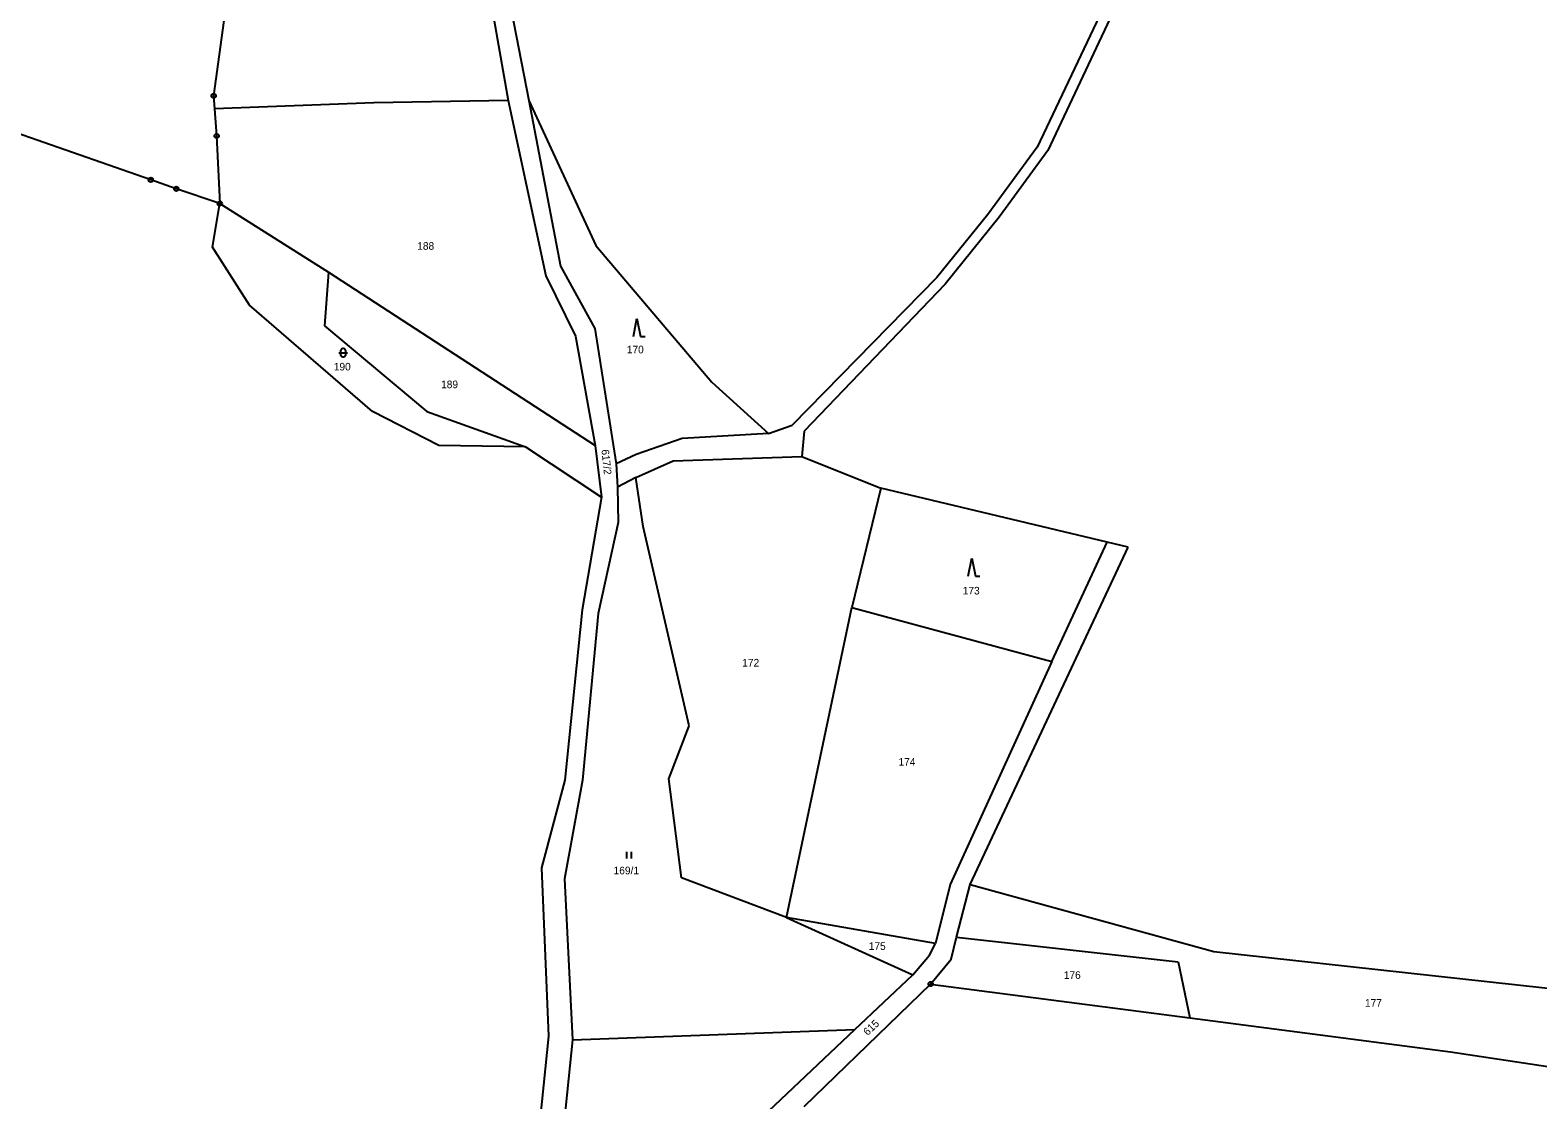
# Model space of a CAD drawing. Extents: x -794421 to -792735, y -1117671 to -1115559.
# Drawn here: x -793585 to -793247.9, y -1116038.2 to -1115798.8 of the extents above; entities that cross this region are included whole.
import ezdxf

# ---------------------------------------------------------------- set-up
doc = ezdxf.new("R2010")
doc.units = 0
for name, color, linetype in [('Vrstva 1', 7, 'Continuous'), ('Vrstva 14', 7, 'Continuous'), ('Vrstva 23', 7, 'Continuous'), ('Vrstva 28', 7, 'Continuous'), ('Vrstva 3', 7, 'Continuous')]:
    doc.layers.add(name, color=color, linetype=linetype)

msp = doc.modelspace()

# ---------------------------------------------------------------- linework, layer by layer
at = {"layer": 'Vrstva 1'}
for p, q in [((-793485.36, -1115773.22), (-793478.09, -1115814.58)), ((-793480.65, -1115777.84), (-793473.46, -1115814.55)), ((-793339.86, -1115782.82), (-793359.82, -1115825.02)), ((-793338.19, -1115784.82), (-793357.42, -1115825.77)), ((-793508.11, -1115815.07), (-793543.74, -1115816.4)), ((-793478.09, -1115814.58), (-793508.11, -1115815.07)), ((-793478.09, -1115814.58), (-793469.7, -1115853.81)), ((-793473.46, -1115814.55), (-793458.47, -1115847)), ((-793473.46, -1115814.55), (-793466.4, -1115851.61)), ((-793359.82, -1115825.02), (-793370.88, -1115840.05)), ((-793357.42, -1115825.77), (-793368.35, -1115840.67)), ((-793544.23, -1115847.41), (-793542.58, -1115837.63)), ((-793542.58, -1115837.63), (-793518.28, -1115852.96)), ((-793370.88, -1115840.05), (-793382.22, -1115854.19)), ((-793368.35, -1115840.67), (-793380.36, -1115855.63)), ((-793535.96, -1115860.33), (-793544.23, -1115847.41)), ((-793458.47, -1115847), (-793432.58, -1115877.58)), ((-793518.28, -1115852.96), (-793519.18, -1115864.98)), ((-793518.28, -1115852.96), (-793458.62, -1115891.74)), ((-793466.4, -1115851.61), (-793458.72, -1115865.58)), ((-793469.7, -1115853.81), (-793463.03, -1115867.31)), ((-793382.22, -1115854.19), (-793414.57, -1115887.19)), ((-793380.36, -1115855.63), (-793411.9, -1115888.53)), ((-793508.42, -1115884.14), (-793535.96, -1115860.33)), ((-793519.18, -1115864.98), (-793496.3, -1115884.14)), ((-793458.72, -1115865.58), (-793453.93, -1115895.86)), ((-793463.03, -1115867.31), (-793458.62, -1115891.74)), ((-793432.58, -1115877.58), (-793419.86, -1115889.08)), ((-793493.58, -1115891.74), (-793508.42, -1115884.14)), ((-793496.3, -1115884.14), (-793474.2, -1115892.08)), ((-793439.19, -1115890.2), (-793449.48, -1115893.78)), ((-793419.86, -1115889.08), (-793439.19, -1115890.2)), ((-793419.86, -1115889.08), (-793414.57, -1115887.19)), ((-793411.9, -1115888.53), (-793412.45, -1115894.24)), ((-793474.2, -1115892.08), (-793493.58, -1115891.74)), ((-793474.2, -1115892.08), (-793457.22, -1115903.34)), ((-793458.62, -1115891.74), (-793457.22, -1115903.34)), ((-793449.48, -1115893.78), (-793453.93, -1115895.86)), ((-793453.93, -1115895.86), (-793453.64, -1115901.04)), ((-793449.54, -1115898.9), (-793441.19, -1115895.21)), ((-793441.19, -1115895.21), (-793412.45, -1115894.24)), ((-793412.45, -1115894.24), (-793394.77, -1115901.29)), ((-793449.54, -1115898.9), (-793453.64, -1115901.04)), ((-793447.91, -1115909.87), (-793449.54, -1115898.9)), ((-793457.22, -1115903.34), (-793461.59, -1115928.51)), ((-793453.64, -1115901.04), (-793453.47, -1115909.01)), ((-793394.77, -1115901.29), (-793401.27, -1115927.99)), ((-793344.15, -1115913.41), (-793394.77, -1115901.29)), ((-793453.47, -1115909.01), (-793457.95, -1115929.34)), ((-793437.63, -1115954.44), (-793447.91, -1115909.87)), ((-793356.51, -1115940.1), (-793344.15, -1115913.41)), ((-793339.48, -1115914.51), (-793344.15, -1115913.41)), ((-793374.77, -1115989.99), (-793339.48, -1115914.51)), ((-793461.59, -1115928.51), (-793465.42, -1115966.65)), ((-793457.95, -1115929.34), (-793461.46, -1115966.64)), ((-793415.89, -1115997.34), (-793401.27, -1115927.99)), ((-793401.27, -1115927.99), (-793356.51, -1115940.1)), ((-793356.51, -1115940.1), (-793379.29, -1115989.96)), ((-793442.14, -1115966.35), (-793437.63, -1115954.44)), ((-793465.42, -1115966.65), (-793470.63, -1115986.21)), ((-793461.46, -1115966.64), (-793465.47, -1115988.73)), ((-793439.35, -1115988.48), (-793442.14, -1115966.35)), ((-793470.63, -1115986.21), (-793469.1, -1116023.94)), ((-793465.47, -1115988.73), (-793463.7, -1116024.71)), ((-793415.89, -1115997.34), (-793439.35, -1115988.48)), ((-793379.29, -1115989.96), (-793382.55, -1116003.19)), ((-793377.84, -1116001.78), (-793374.77, -1115989.99)), ((-793374.77, -1115989.99), (-793320.32, -1116004.97)), ((-793415.89, -1115997.34), (-793387.65, -1116010.16)), ((-793382.55, -1116003.19), (-793415.89, -1115997.34)), ((-793383.9, -1116005.81), (-793382.55, -1116003.19)), ((-793379.05, -1116006.7), (-793377.84, -1116001.78)), ((-793377.84, -1116001.78), (-793328.28, -1116007.26)), ((-793320.32, -1116004.97), (-793237.85, -1116014.01)), ((-793387.65, -1116010.16), (-793383.9, -1116005.81)), ((-793383.64, -1116012.24), (-793379.05, -1116006.7)), ((-793328.28, -1116007.26), (-793325.68, -1116019.79)), ((-793400.57, -1116022.38), (-793387.65, -1116010.16)), ((-793469.1, -1116023.94), (-793475.64, -1116087.76)), ((-793463.7, -1116024.71), (-793470.75, -1116092.14)), ((-793463.7, -1116024.71), (-793400.57, -1116022.38)), ((-793433.69, -1116053.72), (-793400.57, -1116022.38))]:
    msp.add_line(p, q, dxfattribs=at)
at = {"layer": 'Vrstva 23'}
for p, q in [((-793450.1, -1115867.37), (-793449.3, -1115863.37)), ((-793449.3, -1115863.37), (-793448.5, -1115867.37)), ((-793515.49, -1115870.41), (-793515.39, -1115870.21)), ((-793515.39, -1115870.21), (-793515.29, -1115870.11)), ((-793515.29, -1115870.11), (-793515.09, -1115870.01)), ((-793515.09, -1115870.01), (-793514.89, -1115870.01)), ((-793514.89, -1115870.01), (-793514.69, -1115870.11)), ((-793514.69, -1115870.11), (-793514.59, -1115870.21)), ((-793514.59, -1115870.21), (-793514.49, -1115870.41)), ((-793448.5, -1115867.37), (-793447.5, -1115867.37)), ((-793515.99, -1115871.01), (-793513.99, -1115871.01)), ((-793515.49, -1115871.61), (-793515.49, -1115870.41)), ((-793515.39, -1115871.81), (-793515.49, -1115871.61)), ((-793515.29, -1115871.91), (-793515.39, -1115871.81)), ((-793515.09, -1115872.01), (-793515.29, -1115871.91)), ((-793514.89, -1115872.01), (-793515.09, -1115872.01)), ((-793514.69, -1115871.91), (-793514.89, -1115872.01)), ((-793514.59, -1115871.81), (-793514.69, -1115871.91)), ((-793514.49, -1115871.61), (-793514.59, -1115871.81)), ((-793514.49, -1115870.41), (-793514.49, -1115871.61)), ((-793375.24, -1115920.99), (-793374.44, -1115916.99)), ((-793374.44, -1115916.99), (-793373.64, -1115920.99)), ((-793373.64, -1115920.99), (-793372.64, -1115920.99)), ((-793451.57, -1115984.16), (-793451.57, -1115982.66)), ((-793450.57, -1115982.66), (-793450.57, -1115984.16))]:
    msp.add_line(p, q, dxfattribs=at)
at = {"layer": 'Vrstva 28'}
for centre, radius in [((-793543.95, -1115813.52), 0.5), ((-793543.95, -1115813.52), 0.01), ((-793543.28, -1115822.49), 0.5), ((-793543.28, -1115822.49), 0.01), ((-793557.99, -1115832.33), 0.5), ((-793557.99, -1115832.33), 0.01), ((-793552.31, -1115834.32), 0.5), ((-793552.31, -1115834.32), 0.01), ((-793542.58, -1115837.63), 0.5), ((-793542.58, -1115837.63), 0.01), ((-793383.64, -1116012.24), 0.5), ((-793383.64, -1116012.24), 0.01)]:
    msp.add_circle(centre, radius, dxfattribs=at)
at = {"layer": 'Vrstva 3'}
for p, q in [((-793540.84, -1115790.5), (-793543.95, -1115813.52)), ((-793543.95, -1115813.52), (-793543.74, -1115816.4)), ((-793543.74, -1115816.4), (-793543.28, -1115822.49)), ((-793557.99, -1115832.33), (-793589.84, -1115821.24)), ((-793543.28, -1115822.49), (-793542.58, -1115837.63)), ((-793552.31, -1115834.32), (-793557.99, -1115832.33)), ((-793542.58, -1115837.63), (-793552.31, -1115834.32)), ((-793383.64, -1116012.24), (-793412.01, -1116039.73)), ((-793383.64, -1116012.24), (-793325.68, -1116019.79)), ((-793325.68, -1116019.79), (-793267.43, -1116027.38)), ((-793267.43, -1116027.38), (-793206.71, -1116036.58))]:
    msp.add_line(p, q, dxfattribs=at)

# ---------------------------------------------------------------- texts
at = {"layer": 'Vrstva 14'}
for s, p in [('188', (-793498.43, -1115847.96)), ('170', (-793451.566, -1115871.13)), ('190', (-793517.089, -1115874.96)), ('189', (-793493.1, -1115878.93)), ('173', (-793376.467, -1115925.08)), ('172', (-793425.766, -1115941.2)), ('174', (-793390.832, -1115963.38)), ('169/1', (-793454.526, -1115987.69)), ('175', (-793397.483, -1116004.61)), ('176', (-793353.877, -1116011.09)), ('177', (-793286.533, -1116017.32))]:
    msp.add_text(s, height=1.7, dxfattribs=at).set_placement(p)
for s, rotation, p in [('617/2', 275.90616, (-793457.249, -1115892.707)), ('615', 42.99876, (-793397.747, -1116023.878))]:
    msp.add_text(s, height=1.7, rotation=rotation, dxfattribs=at).set_placement(p)

doc.saveas('drawing.dxf')
